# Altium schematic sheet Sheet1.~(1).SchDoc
size A
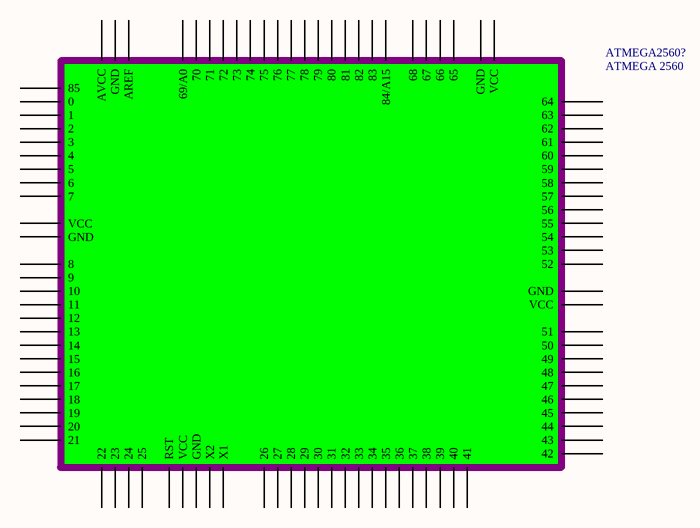
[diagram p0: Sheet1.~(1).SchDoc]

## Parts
ATMEGA2560?  ATMEGA 2560  [ATMEGA 2560]

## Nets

Not connected (* = marked no-connect by the designer): ATMEGA2560? 0 1 2 3 4 5 6 7 8 9 10 11 12 13 14 15 16 17 18 19 20 21 22 23 24 25 26 27 28 29 30 31 32 33 34 35 36 37 38 39 40 41 42 43 44 45 46 47 48 49 50 51 52 53 54 55 56 57 58 59 60 61 62 63 64 65 66 67 68 69(69/A0) 70 71 72 73 74 75 76 77 78 79 80 81 82 83 84(84/A15) 85 AREF AVCC GND RST VCC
